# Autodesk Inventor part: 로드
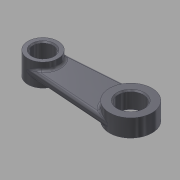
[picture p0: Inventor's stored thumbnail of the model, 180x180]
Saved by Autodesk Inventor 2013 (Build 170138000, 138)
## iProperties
Created: 2015-10
Part Number: 로드
Document SubType Name: Modeling
Designer: mdu
Density: 7.86 g/cm^3
Material: 강철, 연강
Mass: 20.3759 g
Surface Area: 22.2266 cm^2
Volume: 2.59236 cm^3
Author: mdu
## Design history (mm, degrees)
sketch "스케치1"
  geometry: L1 (13.821, 5.985)-(48.643, 8.478); L2 (48.643, -8.478)-(13.821, -5.985); C1 r 4 at (14.25, 0) reference; A1 r 6 centre (14.25, 0) between (13.821, 5.985) and (13.821, -5.985); A2 r 8.5 centre (49.25, 0) between (48.643, 8.478) and (48.643, -8.478); 1 further point
  constraints: 4 end point, 4 point on circle, 4 tangent, 2 centre point, 1 coincident, 1 horizontal alignment
  dimensions: "d0" = 12 diameter of A1; "d1" = 35 distance of A2.centre A1.centre; "d2" = 17 diameter of A2
  node "참조1"
extrude "돌출1" new body sketch "스케치1" distance "d3" = 9; taper "d4" = 0 deg
node "작업 평면1"
node "작업 평면2"
extrude "돌출2" join sketch "스케치1" stored distance "d7" = 10; taper "d8" = 0 deg
node "작업 평면3"
extrude "돌출3" join sketch "스케치1" stored distance "d10" = 10; taper "d11" = 0 deg
hole "구멍1" diameter "d14" = 10; stored, may be unused: countersink angle "d18" = 90 deg, drill point angle "d20" = 118 deg; dims "d12" = 10, "d13" = 10, "d15" = 6, "d16" = 4, "d17" = 2, "d19" = 8
fillet "모깎기1" dims "d21" = 1
chamfer "모따기1" distance "d22" = 0.5; stored, may be unused: second distance "d23" = 2, angle "d24" = 45 deg
chamfer "모따기2" distance "d25" = 0.5; stored, may be unused: second distance "d26" = 2, angle "d27" = 45 deg
node "솔리드1"
other parameters: "d5" = -6, "d6" = -3, "d9" = -4
